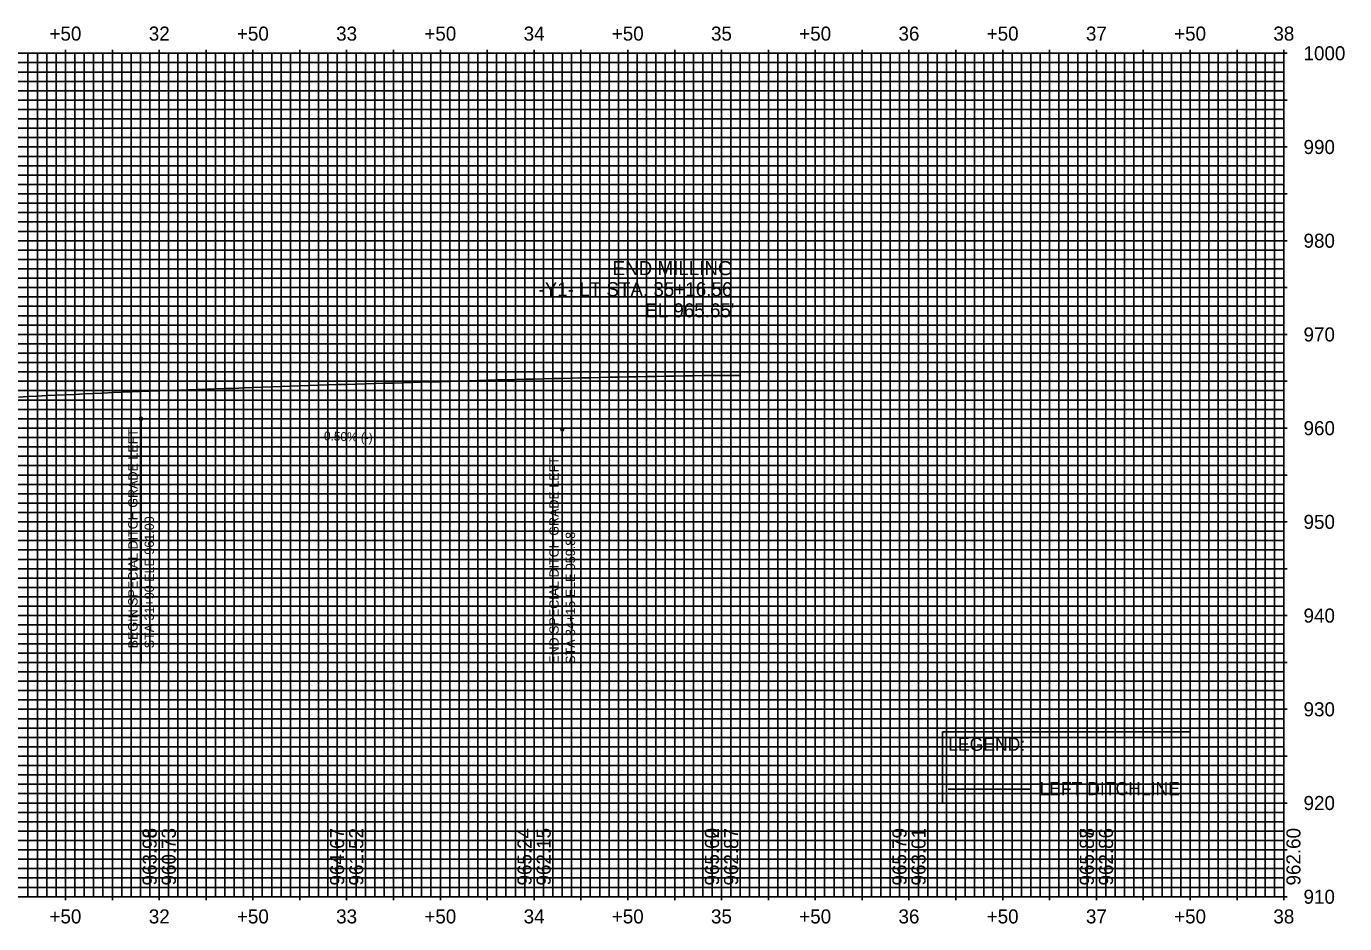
# Model space of a CAD drawing. Extents: x 1367 to 2832, y 896 to 1374.
# Drawn here: x 2129 to 2832, y 896 to 1374 of the extents above; entities that cross this region are included whole.
import ezdxf

# ---------------------------------------------------------------- set-up
doc = ezdxf.new("R2010")
doc.units = 0
for name, color, linetype in [('E_NCDOT_Terrain_Model_Contour_Major', 7, 'Continuous'), ('E_NCDOT_Vertical_Profile_Strip_Grade', 7, 'Continuous'), ('Old_Level_35', 7, 'Continuous'), ('P_NCDOT_Horizontal_Alignment_Curve_and_Spiral_Data', 7, 'Continuous'), ('P_NCDOT_Horizontal_Alignment_Station_Label', 7, 'Continuous'), ('P_NCDOT_Horizontal_Alignment_Station_Major_Label', 7, 'Continuous'), ('P_NCDOT_Horizontal_Alignment_Tick_Large', 7, 'Continuous'), ('P_NCDOT_Horizontal_Alignment_Tick_Small', 7, 'Continuous'), ('P_NCDOT_Vertical_Profile_Ditch_Grade_Left', 7, 'Continuous'), ('P_NCDOT_Vertical_Profile_Ditch_Grade_Left_Label', 7, 'Continuous'), ('P_NCDOT_Vertical_Profile_Ditch_Grade_Right', 7, 'Continuous'), ('P_NCDOT_Vertical_Profile_Strip_Grade', 7, 'Continuous'), ('P_RDY_Profile_Special_Ditch_L', 7, 'Continuous')]:
    doc.layers.add(name, color=color, linetype=linetype)

msp = doc.modelspace()

# ---------------------------------------------------------------- linework, layer by layer
at = {"layer": 'E_NCDOT_Terrain_Model_Contour_Major'}
msp.add_lwpolyline([(2125, 1176.6), (2130, 1176.87), (2135, 1177.12), (2140, 1177.35), (2145, 1177.55), (2150, 1177.73), (2155, 1177.95), (2160, 1178.22), (2165, 1178.46), (2170, 1178.72), (2175, 1178.96), (2180, 1179.18), (2185, 1179.37), (2190, 1179.56), (2195, 1179.74), (2200, 1179.92), (2205, 1180.13), (2210, 1180.3), (2215, 1180.46), (2220, 1180.62), (2225, 1180.76), (2230, 1180.91), (2235, 1181.07), (2240, 1181.24), (2245, 1181.43), (2250, 1181.66), (2255, 1181.86), (2260, 1182.01), (2265, 1182.21), (2270, 1182.39), (2275, 1182.55), (2280, 1182.72), (2285, 1182.88), (2290, 1183.05), (2295, 1183.2), (2300, 1183.37), (2305, 1183.51), (2310, 1183.65), (2315, 1183.79), (2320, 1183.91), (2325, 1184.06), (2330, 1184.22), (2335, 1184.35), (2340, 1184.51), (2345, 1184.65), (2350, 1184.79), (2355, 1184.93), (2360, 1185.08), (2365, 1185.25), (2370, 1185.42), (2375, 1185.55), (2380, 1185.69), (2385, 1185.86), (2390, 1185.97), (2395, 1186.09), (2400, 1186.2), (2405, 1186.32), (2410, 1186.43), (2415, 1186.55), (2420, 1186.67), (2425, 1186.77), (2430, 1186.89), (2435, 1187.03), (2440, 1187.15), (2445, 1187.25), (2450, 1187.34), (2455, 1187.42), (2460, 1187.48), (2465, 1187.6), (2470, 1187.7), (2475, 1187.8), (2480, 1187.9), (2485, 1187.99), (2490, 1188.04), (2495, 1188.09), (2500, 1188.11), (2505, 1188.13), (2510, 1188.16)], dxfattribs=at)
at = {"layer": 'Old_Level_35'}
msp.add_lwpolyline([(2617.89, 997.96), (2750, 997.96), (2750, 960), (2617.89, 960)], close=True, dxfattribs=at)
at = {"layer": 'P_NCDOT_Horizontal_Alignment_Station_Label'}
for p, q in [((2150, 910), (2150, 1360)), ((2200, 910), (2200, 1360)), ((2250, 910), (2250, 1360)), ((2300, 910), (2300, 1360)), ((2350, 910), (2350, 1360)), ((2400, 910), (2400, 1360)), ((2450, 910), (2450, 1360)), ((2500, 910), (2500, 1360)), ((2550, 910), (2550, 1360)), ((2600, 910), (2600, 1360)), ((2650, 910), (2650, 1360)), ((2700, 910), (2700, 1360)), ((2750, 910), (2750, 1360)), ((1400, 1310), (2800, 1310)), ((1400, 1260), (2800, 1260)), ((1400, 1210), (2800, 1210)), ((1400, 1160), (2800, 1160)), ((1400, 1110), (2800, 1110)), ((1400, 1060), (2800, 1060)), ((1400, 1010), (2800, 1010)), ((1400, 960), (2800, 960))]:
    msp.add_line(p, q, dxfattribs=at)
at = {"layer": 'P_NCDOT_Horizontal_Alignment_Station_Major_Label'}
for p, q in [((2130, 910), (2130, 1360)), ((2135, 910), (2135, 1360)), ((2140, 910), (2140, 1360)), ((2145, 910), (2145, 1360)), ((2155, 910), (2155, 1360)), ((2160, 910), (2160, 1360)), ((2165, 910), (2165, 1360)), ((2170, 910), (2170, 1360)), ((2180, 910), (2180, 1360)), ((2185, 910), (2185, 1360)), ((2190, 910), (2190, 1360)), ((2195, 910), (2195, 1360)), ((2205, 910), (2205, 1360)), ((2210, 910), (2210, 1360)), ((2215, 910), (2215, 1360)), ((2220, 910), (2220, 1360)), ((2230, 910), (2230, 1360)), ((2235, 910), (2235, 1360)), ((2240, 910), (2240, 1360)), ((2245, 910), (2245, 1360)), ((2255, 910), (2255, 1360)), ((2260, 910), (2260, 1360)), ((2265, 910), (2265, 1360)), ((2270, 910), (2270, 1360)), ((2280, 910), (2280, 1360)), ((2285, 910), (2285, 1360)), ((2290, 910), (2290, 1360)), ((2295, 910), (2295, 1360)), ((2305, 910), (2305, 1360)), ((2310, 910), (2310, 1360)), ((2315, 910), (2315, 1360)), ((2320, 910), (2320, 1360)), ((2330, 910), (2330, 1360)), ((2335, 910), (2335, 1360)), ((2340, 910), (2340, 1360)), ((2345, 910), (2345, 1360)), ((2355, 910), (2355, 1360)), ((2360, 910), (2360, 1360)), ((2365, 910), (2365, 1360)), ((2370, 910), (2370, 1360)), ((2380, 910), (2380, 1360)), ((2385, 910), (2385, 1360)), ((2390, 910), (2390, 1360)), ((2395, 910), (2395, 1360)), ((2405, 910), (2405, 1360)), ((2410, 910), (2410, 1360)), ((2415, 910), (2415, 1360)), ((2420, 910), (2420, 1360)), ((2430, 910), (2430, 1360)), ((2435, 910), (2435, 1360)), ((2440, 910), (2440, 1360)), ((2445, 910), (2445, 1360)), ((2455, 910), (2455, 1360)), ((2460, 910), (2460, 1360)), ((2465, 910), (2465, 1360)), ((2470, 910), (2470, 1360)), ((2480, 910), (2480, 1360)), ((2485, 910), (2485, 1360)), ((2490, 910), (2490, 1360)), ((2495, 910), (2495, 1360)), ((2505, 910), (2505, 1360)), ((2510, 910), (2510, 1360)), ((2515, 910), (2515, 1360)), ((2520, 910), (2520, 1360)), ((2530, 910), (2530, 1360)), ((2535, 910), (2535, 1360)), ((2540, 910), (2540, 1360)), ((2545, 910), (2545, 1360)), ((2555, 910), (2555, 1360)), ((2560, 910), (2560, 1360)), ((2565, 910), (2565, 1360)), ((2570, 910), (2570, 1360)), ((2580, 910), (2580, 1360)), ((2585, 910), (2585, 1360)), ((2590, 910), (2590, 1360)), ((2595, 910), (2595, 1360)), ((2605, 910), (2605, 1360)), ((2610, 910), (2610, 1360)), ((2615, 910), (2615, 1360)), ((2620, 910), (2620, 1360)), ((2630, 910), (2630, 1360)), ((2635, 910), (2635, 1360)), ((2640, 910), (2640, 1360)), ((2645, 910), (2645, 1360)), ((2655, 910), (2655, 1360)), ((2660, 910), (2660, 1360)), ((2665, 910), (2665, 1360)), ((2670, 910), (2670, 1360)), ((2680, 910), (2680, 1360)), ((2685, 910), (2685, 1360)), ((2690, 910), (2690, 1360)), ((2695, 910), (2695, 1360)), ((2705, 910), (2705, 1360)), ((2710, 910), (2710, 1360)), ((2715, 910), (2715, 1360)), ((2720, 910), (2720, 1360)), ((2730, 910), (2730, 1360)), ((2735, 910), (2735, 1360)), ((2740, 910), (2740, 1360)), ((2745, 910), (2745, 1360)), ((2755, 910), (2755, 1360)), ((2760, 910), (2760, 1360)), ((2765, 910), (2765, 1360)), ((2770, 910), (2770, 1360)), ((2780, 910), (2780, 1360)), ((2785, 910), (2785, 1360)), ((2790, 910), (2790, 1360)), ((2795, 910), (2795, 1360)), ((1400, 1355), (2800, 1355)), ((1400, 1350), (2800, 1350)), ((1400, 1345), (2800, 1345)), ((1400, 1340), (2800, 1340)), ((1400, 1330), (2800, 1330)), ((1400, 1325), (2800, 1325)), ((1400, 1320), (2800, 1320)), ((1400, 1315), (2800, 1315)), ((1400, 1305), (2800, 1305)), ((1400, 1300), (2800, 1300)), ((1400, 1295), (2800, 1295)), ((1400, 1290), (2800, 1290)), ((1400, 1280), (2800, 1280)), ((1400, 1275), (2800, 1275)), ((1400, 1270), (2800, 1270)), ((1400, 1265), (2800, 1265)), ((1400, 1255), (2800, 1255)), ((1400, 1250), (2800, 1250)), ((1400, 1245), (2800, 1245)), ((1400, 1240), (2800, 1240)), ((1400, 1230), (2800, 1230)), ((1400, 1225), (2800, 1225)), ((1400, 1220), (2800, 1220)), ((1400, 1215), (2800, 1215)), ((1400, 1205), (2800, 1205)), ((1400, 1200), (2800, 1200)), ((1400, 1195), (2800, 1195)), ((1400, 1190), (2800, 1190)), ((1400, 1180), (2800, 1180)), ((1400, 1175), (2800, 1175)), ((1400, 1170), (2800, 1170)), ((1400, 1165), (2800, 1165)), ((1400, 1155), (2800, 1155)), ((1400, 1150), (2800, 1150)), ((1400, 1145), (2800, 1145)), ((1400, 1140), (2800, 1140)), ((1400, 1130), (2800, 1130)), ((1400, 1125), (2800, 1125)), ((1400, 1120), (2800, 1120)), ((1400, 1115), (2800, 1115)), ((1400, 1105), (2800, 1105)), ((1400, 1100), (2800, 1100)), ((1400, 1095), (2800, 1095)), ((1400, 1090), (2800, 1090)), ((1400, 1080), (2800, 1080)), ((1400, 1075), (2800, 1075)), ((1400, 1070), (2800, 1070)), ((1400, 1065), (2800, 1065)), ((1400, 1055), (2800, 1055)), ((1400, 1050), (2800, 1050)), ((1400, 1045), (2800, 1045)), ((1400, 1040), (2800, 1040)), ((1400, 1030), (2800, 1030)), ((1400, 1025), (2800, 1025)), ((1400, 1020), (2800, 1020)), ((1400, 1015), (2800, 1015)), ((1400, 1005), (2800, 1005)), ((1400, 1000), (2800, 1000)), ((1400, 995), (2800, 995)), ((1400, 990), (2800, 990)), ((1400, 980), (2800, 980)), ((1400, 975), (2800, 975)), ((1400, 970), (2800, 970)), ((1400, 965), (2800, 965)), ((1400, 955), (2800, 955)), ((1400, 950), (2800, 950)), ((1400, 945), (2800, 945)), ((1400, 940), (2800, 940)), ((1400, 930), (2800, 930)), ((1400, 925), (2800, 925)), ((1400, 920), (2800, 920)), ((1400, 915), (2800, 915))]:
    msp.add_line(p, q, dxfattribs=at)
at = {"layer": 'P_NCDOT_Horizontal_Alignment_Tick_Large'}
for p, q in [((2150, 1361.8), (2150, 1360)), ((2150, 910), (2150, 1360)), ((2175, 1361.8), (2175, 1360)), ((2175, 910), (2175, 1360)), ((2200, 1361.8), (2200, 1360)), ((2200, 910), (2200, 1360)), ((2225, 1361.8), (2225, 1360)), ((2225, 910), (2225, 1360)), ((2250, 1361.8), (2250, 1360)), ((2250, 910), (2250, 1360)), ((2275, 1361.8), (2275, 1360)), ((2275, 910), (2275, 1360)), ((2300, 1361.8), (2300, 1360)), ((2300, 910), (2300, 1360)), ((2325, 1361.8), (2325, 1360)), ((2325, 910), (2325, 1360)), ((2350, 1361.8), (2350, 1360)), ((2350, 910), (2350, 1360)), ((2375, 1361.8), (2375, 1360)), ((2375, 910), (2375, 1360)), ((2400, 1361.8), (2400, 1360)), ((2400, 910), (2400, 1360)), ((2425, 1361.8), (2425, 1360)), ((2425, 910), (2425, 1360)), ((2450, 1361.8), (2450, 1360)), ((2450, 910), (2450, 1360)), ((2475, 1361.8), (2475, 1360)), ((2475, 910), (2475, 1360)), ((2500, 1361.8), (2500, 1360)), ((2500, 910), (2500, 1360)), ((2525, 1361.8), (2525, 1360)), ((2525, 910), (2525, 1360)), ((2550, 1361.8), (2550, 1360)), ((2550, 910), (2550, 1360)), ((2575, 1361.8), (2575, 1360)), ((2575, 910), (2575, 1360)), ((2600, 1361.8), (2600, 1360)), ((2600, 910), (2600, 1360)), ((2625, 1361.8), (2625, 1360)), ((2625, 910), (2625, 1360)), ((2650, 1361.8), (2650, 1360)), ((2650, 910), (2650, 1360)), ((2675, 1361.8), (2675, 1360)), ((2675, 910), (2675, 1360)), ((2700, 1361.8), (2700, 1360)), ((2700, 910), (2700, 1360)), ((2725, 1361.8), (2725, 1360)), ((2725, 910), (2725, 1360)), ((2750, 1361.8), (2750, 1360)), ((2750, 910), (2750, 1360)), ((2775, 1361.8), (2775, 1360)), ((2775, 910), (2775, 1360)), ((2800, 1361.8), (2800, 1360)), ((2801.8, 1360), (2800, 1360)), ((1400, 1335), (2800, 1335)), ((2801.8, 1335), (2800, 1335)), ((1400, 1310), (2800, 1310)), ((2801.8, 1310), (2800, 1310)), ((1400, 1285), (2800, 1285)), ((2801.8, 1285), (2800, 1285)), ((1400, 1260), (2800, 1260)), ((2801.8, 1260), (2800, 1260)), ((1400, 1235), (2800, 1235)), ((2801.8, 1235), (2800, 1235)), ((1400, 1210), (2800, 1210)), ((2801.8, 1210), (2800, 1210)), ((1400, 1185), (2800, 1185)), ((2801.8, 1185), (2800, 1185)), ((1400, 1160), (2800, 1160)), ((2801.8, 1160), (2800, 1160)), ((1400, 1135), (2800, 1135)), ((2801.8, 1135), (2800, 1135)), ((1400, 1110), (2800, 1110)), ((2801.8, 1110), (2800, 1110)), ((1400, 1085), (2800, 1085)), ((2801.8, 1085), (2800, 1085)), ((1400, 1060), (2800, 1060)), ((2801.8, 1060), (2800, 1060)), ((1400, 1035), (2800, 1035)), ((2801.8, 1035), (2800, 1035)), ((1400, 1010), (2800, 1010)), ((2801.8, 1010), (2800, 1010)), ((1400, 985), (2800, 985)), ((2801.8, 985), (2800, 985)), ((1400, 960), (2800, 960)), ((2801.8, 960), (2800, 960)), ((1400, 935), (2800, 935)), ((2801.8, 935), (2800, 935)), ((2150, 910), (2150, 908.2)), ((2175, 910), (2175, 908.2)), ((2200, 910), (2200, 908.2)), ((2225, 910), (2225, 908.2)), ((2250, 910), (2250, 908.2)), ((2275, 910), (2275, 908.2)), ((2300, 910), (2300, 908.2)), ((2325, 910), (2325, 908.2)), ((2350, 910), (2350, 908.2)), ((2375, 910), (2375, 908.2)), ((2400, 910), (2400, 908.2)), ((2425, 910), (2425, 908.2)), ((2450, 910), (2450, 908.2)), ((2475, 910), (2475, 908.2)), ((2500, 910), (2500, 908.2)), ((2525, 910), (2525, 908.2)), ((2550, 910), (2550, 908.2)), ((2575, 910), (2575, 908.2)), ((2600, 910), (2600, 908.2)), ((2625, 910), (2625, 908.2)), ((2650, 910), (2650, 908.2)), ((2675, 910), (2675, 908.2)), ((2700, 910), (2700, 908.2)), ((2725, 910), (2725, 908.2)), ((2750, 910), (2750, 908.2)), ((2775, 910), (2775, 908.2)), ((2800, 910), (2800, 908.2)), ((2801.8, 910), (2800, 910))]:
    msp.add_line(p, q, dxfattribs=at)
at = {"layer": 'P_NCDOT_Horizontal_Alignment_Tick_Small'}
for p, q in [((1400, 1360), (2800, 1360)), ((2800, 910), (2800, 1360)), ((1400, 910), (2800, 910))]:
    msp.add_line(p, q, dxfattribs=at)
at = {"layer": 'P_NCDOT_Vertical_Profile_Ditch_Grade_Left'}
msp.add_line((2620.92, 967.35), (2664.97, 967.35), dxfattribs=at)
at = {"layer": 'P_NCDOT_Vertical_Profile_Ditch_Grade_Left_Label'}
for p, q in [((2190.33, 1165), (2190.33, 1034.42)), ((2415, 1159.38), (2415, 1028.8))]:
    msp.add_line(p, q, dxfattribs=at)
for centre in [(2190.33, 1165), (2415, 1159.38)]:
    msp.add_circle(centre, 0.82, dxfattribs=at)
at = {"layer": 'P_NCDOT_Vertical_Profile_Ditch_Grade_Right'}
for p, q in [((2510, 1240), (2400, 1240)), ((2510, 1188.09), (2510, 1240))]:
    msp.add_line(p, q, dxfattribs=at)

# ---------------------------------------------------------------- texts
at = {"layer": 'E_NCDOT_Vertical_Profile_Strip_Grade'}
for s, p in [('960.73', (2208.85, 916)), ('961.52', (2308.84, 916)), ('962.15', (2408.85, 916)), ('962.87', (2508.83, 916)), ('963.01', (2608.85, 916)), ('962.86', (2708.85, 916)), ('962.60', (2808.85, 916))]:
    msp.add_text(s, height=7.5, rotation=90, dxfattribs=at).set_placement(p)
at = {"layer": 'Old_Level_35'}
for s, p in [('LEGEND:', (2620.92, 987.85)), ('LEFT DITCHLINE', (2669.61, 964.18))]:
    msp.add_text(s, height=7, rotation=360, dxfattribs=at).set_placement(p)
at = {"layer": 'P_NCDOT_Horizontal_Alignment_Curve_and_Spiral_Data'}
for s, p in [('+50', (2141.46, 1366.75)), ('32', (2194.45, 1366.75)), ('+50', (2241.46, 1366.75)), ('33', (2294.41, 1366.75)), ('+50', (2341.46, 1366.75)), ('34', (2394.43, 1366.75)), ('+50', (2441.46, 1366.75)), ('35', (2494.38, 1366.75)), ('+50', (2541.46, 1366.75)), ('36', (2594.41, 1366.75)), ('+50', (2641.46, 1366.75)), ('37', (2694.41, 1366.75)), ('+50', (2741.46, 1366.75)), ('38', (2794.41, 1366.75)), ('+50', (2141.46, 895.75)), ('32', (2194.45, 895.75)), ('+50', (2241.46, 895.75)), ('33', (2294.41, 895.75)), ('+50', (2341.46, 895.75)), ('34', (2394.43, 895.75)), ('+50', (2441.46, 895.75)), ('35', (2494.38, 895.75)), ('+50', (2541.46, 895.75)), ('36', (2594.41, 895.75)), ('+50', (2641.46, 895.75)), ('37', (2694.41, 895.75)), ('+50', (2741.46, 895.75)), ('38', (2794.41, 895.75))]:
    msp.add_text(s, height=7.5, dxfattribs=at).set_placement(p)
at = {"layer": 'P_NCDOT_Vertical_Profile_Ditch_Grade_Left_Label'}
for s, height, rotation, p in [('BEGIN SPECIAL DITCH GRADE LEFT', 5, 90, (2188.46, 1042.51)), ('0.50% (-)', 4.724, 357.85706, (2287.84, 1153.56)), ('END SPECIAL DITCH GRADE LEFT', 5, 90, (2413.13, 1034.24)), ('STA 31+90 ELE 961.00', 5, 90, (2197.2, 1042.51)), ('STA 34+15 ELE 959.88', 5, 90, (2421.87, 1034.24))]:
    msp.add_text(s, height=height, rotation=rotation, dxfattribs=at).set_placement(p)
at = {"layer": 'P_NCDOT_Vertical_Profile_Ditch_Grade_Right'}
for s, p in [('END MILLING', (2441.84, 1241.62)), ('-Y1- LT STA. 35+16.56', (2402.34, 1230.37)), ("EL 965.65'", (2459.25, 1219.12))]:
    msp.add_text(s, height=7.5, dxfattribs=at).set_placement(p)
at = {"layer": 'P_NCDOT_Vertical_Profile_Strip_Grade'}
for s, p in [('963.98', (2198.65, 916)), ('963.96', (2198.65, 916)), ('964.67', (2298.65, 916)), ('964.67', (2298.65, 916)), ('965.24', (2398.65, 916)), ('965.24', (2398.65, 916)), ('965.60', (2498.65, 916)), ('965.62', (2498.65, 916)), ('965.79', (2598.65, 916)), ('965.79', (2598.65, 916)), ('965.88', (2698.65, 916)), ('965.88', (2698.65, 916)), ('965.87', (2698.65, 916)), ('965.87', (2698.65, 916))]:
    msp.add_text(s, height=7.5, rotation=90, dxfattribs=at).set_placement(p)
at = {"layer": 'P_RDY_Profile_Special_Ditch_L'}
for s, p in [('1000', (2810.5, 1356.25)), ('990', (2810.5, 1306.25)), ('980', (2810.5, 1256.25)), ('970', (2810.5, 1206.25)), ('960', (2810.5, 1156.25)), ('950', (2810.5, 1106.25)), ('940', (2810.5, 1056.25)), ('930', (2810.5, 1006.25)), ('920', (2810.5, 956.25)), ('910', (2810.5, 906.25))]:
    msp.add_text(s, height=7.5, dxfattribs=at).set_placement(p)

doc.saveas('drawing.dxf')
